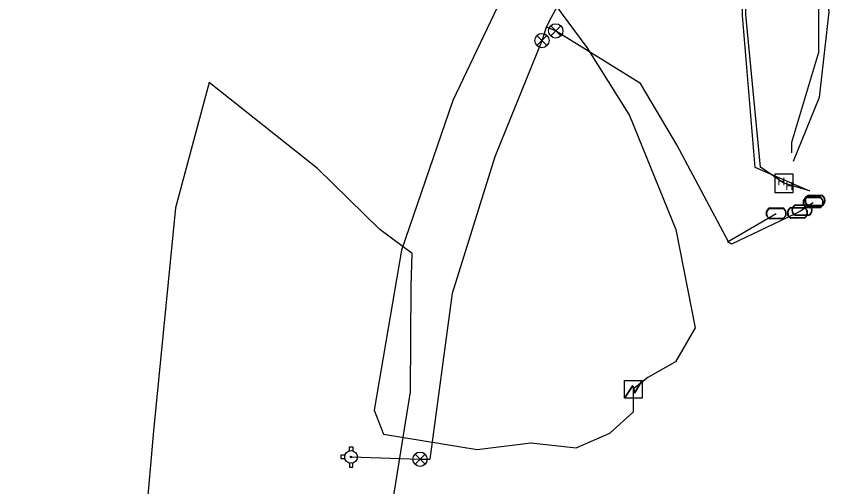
# Model space of a CAD drawing. Extents: x 2070721 to 2083340, y 729290 to 737883.
# Drawn here: x 2080544.7 to 2080798.5, y 734354.5 to 734501.5 of the extents above; entities that cross this region are included whole.
import ezdxf

# ---------------------------------------------------------------- set-up
doc = ezdxf.new("R2010")
doc.units = 0
for name, color, linetype in [('Exist Utilities Power Transformer CELL', 7, 'Continuous'), ('Exist Utilities Power UG Cable SUE LOS B', 7, 'Continuous'), ('Exist Utilities Telephone UG Cable SUE LOS C', 7, 'Continuous'), ('Exist Utilities Telephone UG FO SUE LOS B', 7, 'Continuous'), ('Exist Utilities Telephone UG FO SUE LOS C', 7, 'Continuous'), ('Exist Utilities TV Hand Hole CELL', 7, 'Continuous'), ('Exist Utilities TV UG FO Cable SUE LOS B', 7, 'Continuous'), ('Exist Utilities Water Fire Hydrant CELL', 7, 'Continuous'), ('Exist Utilities Water Meter CELL', 7, 'Continuous'), ('Exist Utilities Water UG Line SUE LOS B', 7, 'Continuous'), ('Exist Utilities Water Valve CELL', 7, 'Continuous')]:
    doc.layers.add(name, color=color, linetype=linetype)

msp = doc.modelspace()

# ---------------------------------------------------------------- linework, layer by layer
at = {"layer": 'Exist Utilities Power Transformer CELL'}
msp.add_line((2080737.52, 734385.1), (2080737.52, 734385.1), dxfattribs=at)
msp.add_lwpolyline([(2080734.68, 734387.71), (2080740.23, 734387.71), (2080740.23, 734382.16), (2080734.68, 734382.16)], close=True, dxfattribs=at)
for points in [[(2080734.68, 734382.16), (2080737.32, 734386.11), (2080737.95, 734383.9), (2080740.23, 734387.71)], [(2080734.75, 734382.16), (2080737.32, 734385.9), (2080737.91, 734383.71), (2080740.23, 734387.56)]]:
    msp.add_lwpolyline(points, dxfattribs=at)
at = {"layer": 'Exist Utilities Power UG Cable SUE LOS B'}
for points in [[(2080667.78, 734563.47), (2080675.67, 734558.83), (2080693.85, 734531.06), (2080722.9, 734491.66), (2080736.23, 734470.41), (2080750.76, 734434.85), (2080756.8, 734404.17), (2080750.61, 734393.55), (2080741.92, 734388.6), (2080737.52, 734385.1)], [(2080697.31, 734510.51), (2080697.15, 734508.83), (2080681.13, 734475.16), (2080665.04, 734428.4), (2080656.55, 734378.37), (2080659.43, 734370.95), (2080688.68, 734366.16), (2080705.41, 734368.17), (2080719.63, 734366.67), (2080730.12, 734371.17), (2080737.52, 734377.9), (2080737.52, 734385.1)], [(2080660.22, 734254.22), (2080665.36, 734271.75), (2080659.75, 734333.73), (2080667.87, 734384.1), (2080668.08, 734417.09), (2080668.36, 734427.32), (2080658.31, 734434.88), (2080638.79, 734453.87), (2080604.95, 734480.75), (2080594.48, 734441.62), (2080587.63, 734371.92), (2080583.9, 734329.12), (2080584.82, 734300.58), (2080593.77, 734266.89), (2080602.76, 734233.65), (2080617.91, 734184.32)]]:
    msp.add_lwpolyline(points, dxfattribs=at)
at = {"layer": 'Exist Utilities Telephone UG Cable SUE LOS C'}
msp.add_lwpolyline([(2080392.43, 734459.45), (2080392.18, 734455.98), (2080369.79, 734491.21), (2080371.64, 734506.16), (2080398.8, 734522.93), (2080423.1, 734536.76), (2080488.87, 734560.43), (2080551.19, 734581.93), (2080605.97, 734600.8), (2080683.17, 734629.37), (2080713.38, 734633.09), (2080745.42, 734609.78), (2080760.77, 734576.63), (2080781.91, 734561.06), (2080789.84, 734547.84), (2080795.45, 734523.96), (2080798.47, 734502.81), (2080795.45, 734476.11), (2080787.39, 734456.13)], dxfattribs=at)
at = {"layer": 'Exist Utilities Telephone UG FO SUE LOS B'}
msp.add_lwpolyline([(2080792.52, 734446.86), (2080775.46, 734454.16), (2080771.57, 734501.71), (2080771.41, 734523.8), (2080772.11, 734540.7), (2080770.17, 734557.91), (2080769.35, 734590.18), (2080775.5, 734606.58), (2080780.96, 734613.32)], dxfattribs=at)
at = {"layer": 'Exist Utilities Telephone UG FO SUE LOS C'}
msp.add_lwpolyline([(2080652.77, 734625.25), (2080667.42, 734617.06), (2080717.34, 734601.19), (2080782.55, 734556.25), (2080795.25, 734516.63), (2080795.25, 734490.1), (2080786.86, 734462.06), (2080786.86, 734458.84)], dxfattribs=at)
at = {"layer": 'Exist Utilities TV Hand Hole CELL'}
msp.add_line((2080784.5, 734449.27), (2080784.5, 734449.27), dxfattribs=at)
msp.add_lwpolyline([(2080781.63, 734446.39), (2080787.38, 734446.39), (2080787.38, 734452.14), (2080781.63, 734452.14), (2080781.63, 734446.39)], dxfattribs=at)
at = {"layer": 'Exist Utilities TV UG FO Cable SUE LOS B'}
msp.add_lwpolyline([(2080792.49, 734446.91), (2080784.46, 734449.31), (2080777.2, 734454.29), (2080772.59, 734502.03), (2080772.98, 734523.68), (2080773.64, 734539.98), (2080772.68, 734584.01), (2080781.47, 734612.06)], dxfattribs=at)
at = {"layer": 'Exist Utilities Water Fire Hydrant CELL'}
msp.add_line((2080649.3, 734363.79), (2080649.3, 734363.79), dxfattribs=at)
for points in [[(2080648.79, 734365.7), (2080648.79, 734366.99), (2080649.82, 734366.99), (2080649.82, 734365.68)], [(2080647.39, 734364.3), (2080646.1, 734364.3), (2080646.1, 734363.28), (2080647.39, 734363.28)], [(2080648.79, 734361.88), (2080648.79, 734360.59), (2080649.82, 734360.59), (2080649.82, 734361.9)]]:
    msp.add_lwpolyline(points, dxfattribs=at)
for radius in [1.98, 0.243]:
    msp.add_circle((2080649.3, 734363.79), radius, dxfattribs=at)
at = {"layer": 'Exist Utilities Water Meter CELL'}
for p, q in [((2080793.61, 734443.32), (2080793.61, 734443.32)), ((2080794.18, 734443.88), (2080794.18, 734443.88)), ((2080788.71, 734440.05), (2080788.71, 734440.05)), ((2080790.11, 734440.87), (2080790.11, 734440.87)), ((2080782.06, 734439.86), (2080782.06, 734439.86))]:
    msp.add_line(p, q, dxfattribs=at)
for points in [[(2080792.14, 734445.58), (2080796.22, 734445.58)], [(2080792.14, 734445.44), (2080796.22, 734445.44)], [(2080788.08, 734442.57), (2080792.15, 734442.57)], [(2080791.57, 734445.02), (2080795.65, 734445.02)], [(2080791.57, 734444.88), (2080795.65, 734444.88)], [(2080780.02, 734441.56), (2080784.1, 734441.56)], [(2080780.02, 734441.43), (2080784.1, 734441.43)], [(2080786.67, 734441.75), (2080790.75, 734441.75)], [(2080786.67, 734441.61), (2080790.75, 734441.61)], [(2080788.08, 734442.43), (2080792.15, 734442.43)], [(2080795.65, 734441.76), (2080791.55, 734441.76)], [(2080795.65, 734441.62), (2080791.55, 734441.62)], [(2080796.22, 734442.31), (2080792.12, 734442.31)], [(2080796.22, 734442.18), (2080792.12, 734442.18)], [(2080784.1, 734438.3), (2080780, 734438.3)], [(2080784.1, 734438.16), (2080780, 734438.16)], [(2080790.75, 734438.49), (2080786.65, 734438.49)], [(2080790.75, 734438.35), (2080786.65, 734438.35)], [(2080792.15, 734439.31), (2080788.05, 734439.31)], [(2080792.15, 734439.17), (2080788.05, 734439.17)]]:
    msp.add_lwpolyline(points, dxfattribs=at)
for centre, radius, start, end in [((2080792.87, 734443.87), 1.86, 113.178, 245.9794), ((2080792.89, 734443.87), 1.73, 115.3009, 243.7824), ((2080795.47, 734443.88), 1.86, 293.6483, 66.3084), ((2080795.49, 734443.88), 1.73, 295.1272, 64.8728), ((2080788.81, 734440.87), 1.86, 113.178, 245.9794), ((2080792.3, 734443.31), 1.86, 113.178, 245.9794), ((2080792.31, 734443.31), 1.73, 115.3009, 243.7824), ((2080791.41, 734440.87), 1.86, 293.6483, 66.3084), ((2080794.9, 734443.32), 1.86, 293.6483, 66.3084), ((2080794.92, 734443.32), 1.73, 295.1272, 64.8728), ((2080780.75, 734439.86), 1.86, 113.178, 245.9794), ((2080780.76, 734439.86), 1.73, 115.3009, 243.7824), ((2080783.35, 734439.87), 1.86, 293.6483, 66.3084), ((2080783.37, 734439.86), 1.73, 295.1272, 64.8728), ((2080787.4, 734440.05), 1.86, 113.178, 245.9794), ((2080787.41, 734440.04), 1.73, 115.3009, 243.7824), ((2080788.82, 734440.87), 1.73, 115.3009, 243.7824), ((2080790, 734440.05), 1.86, 293.6483, 66.3084), ((2080790.01, 734440.05), 1.73, 295.1272, 64.8728), ((2080791.42, 734440.87), 1.73, 295.1272, 64.8728)]:
    msp.add_arc(centre, radius, start, end, dxfattribs=at)
at = {"layer": 'Exist Utilities Water UG Line SUE LOS B'}
for points in [[(2080710.45, 734498.38), (2080711.94, 734501.21), (2080726.31, 734527.8)], [(2080649.3, 734363.85), (2080670.85, 734363.12), (2080674.01, 734363.05), (2080681.01, 734414.95), (2080694.32, 734457.66), (2080708.93, 734493.88), (2080710.45, 734498.38)], [(2080767.17, 734430.94), (2080751.03, 734461.24), (2080739.67, 734480.49), (2080713.13, 734496.9), (2080710.35, 734498.08)], [(2080793.57, 734443.18), (2080789.45, 734440.5), (2080787.79, 734439.62), (2080768.11, 734430.22), (2080766.81, 734431.01), (2080782.06, 734439.79)]]:
    msp.add_lwpolyline(points, dxfattribs=at)
at = {"layer": 'Exist Utilities Water Valve CELL'}
for points in [[(2080714.8, 734498.46), (2080711.65, 734495.31), (2080713.22, 734496.89), (2080714.8, 734495.31), (2080711.65, 734498.46)], [(2080710.47, 734495.45), (2080707.32, 734492.3), (2080708.9, 734493.87), (2080710.47, 734492.3), (2080707.32, 734495.45)], [(2080672.43, 734364.65), (2080669.28, 734361.5), (2080670.85, 734363.08), (2080672.43, 734361.5), (2080669.28, 734364.65)]]:
    msp.add_lwpolyline(points, dxfattribs=at)
for centre in [(2080713.22, 734496.89), (2080708.9, 734493.87), (2080670.85, 734363.08)]:
    msp.add_circle(centre, 2.23, dxfattribs=at)

# ---------------------------------------------------------------- texts
at = {"layer": 'Exist Utilities TV Hand Hole CELL'}
for p in [(2080782.42, 734448.62), (2080784.99, 734447.16)]:
    msp.add_text('H', height=2.5, dxfattribs=at).set_placement(p)

doc.saveas('drawing.dxf')
